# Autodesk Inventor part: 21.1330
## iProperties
Created: 2006-12
Part Number: 21.1330
Document SubType Name: Modeling
Designer: Andy Moles
Material: Steel, Mild
Mass: 4.94212 g
Surface Area: 5.644 cm^2
Volume: 0.628768 cm^3
Density: 7.86 g/cm^3
Description: M6 SQUARE NUT
Author: Andy Moles
Title: M6 SQUARE NUT
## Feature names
1. Extrusion1
2. Revolution1
